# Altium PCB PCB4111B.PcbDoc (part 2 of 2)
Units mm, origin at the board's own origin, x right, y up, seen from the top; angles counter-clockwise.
Board outline 30 x 47 mm, 4 copper layers (Top Layer, Signal Layer 2, Signal Layer 3, Bottom Layer), stack 1.556 mm thick; 81 components, 93 nets, 294 pads, 415 vias.
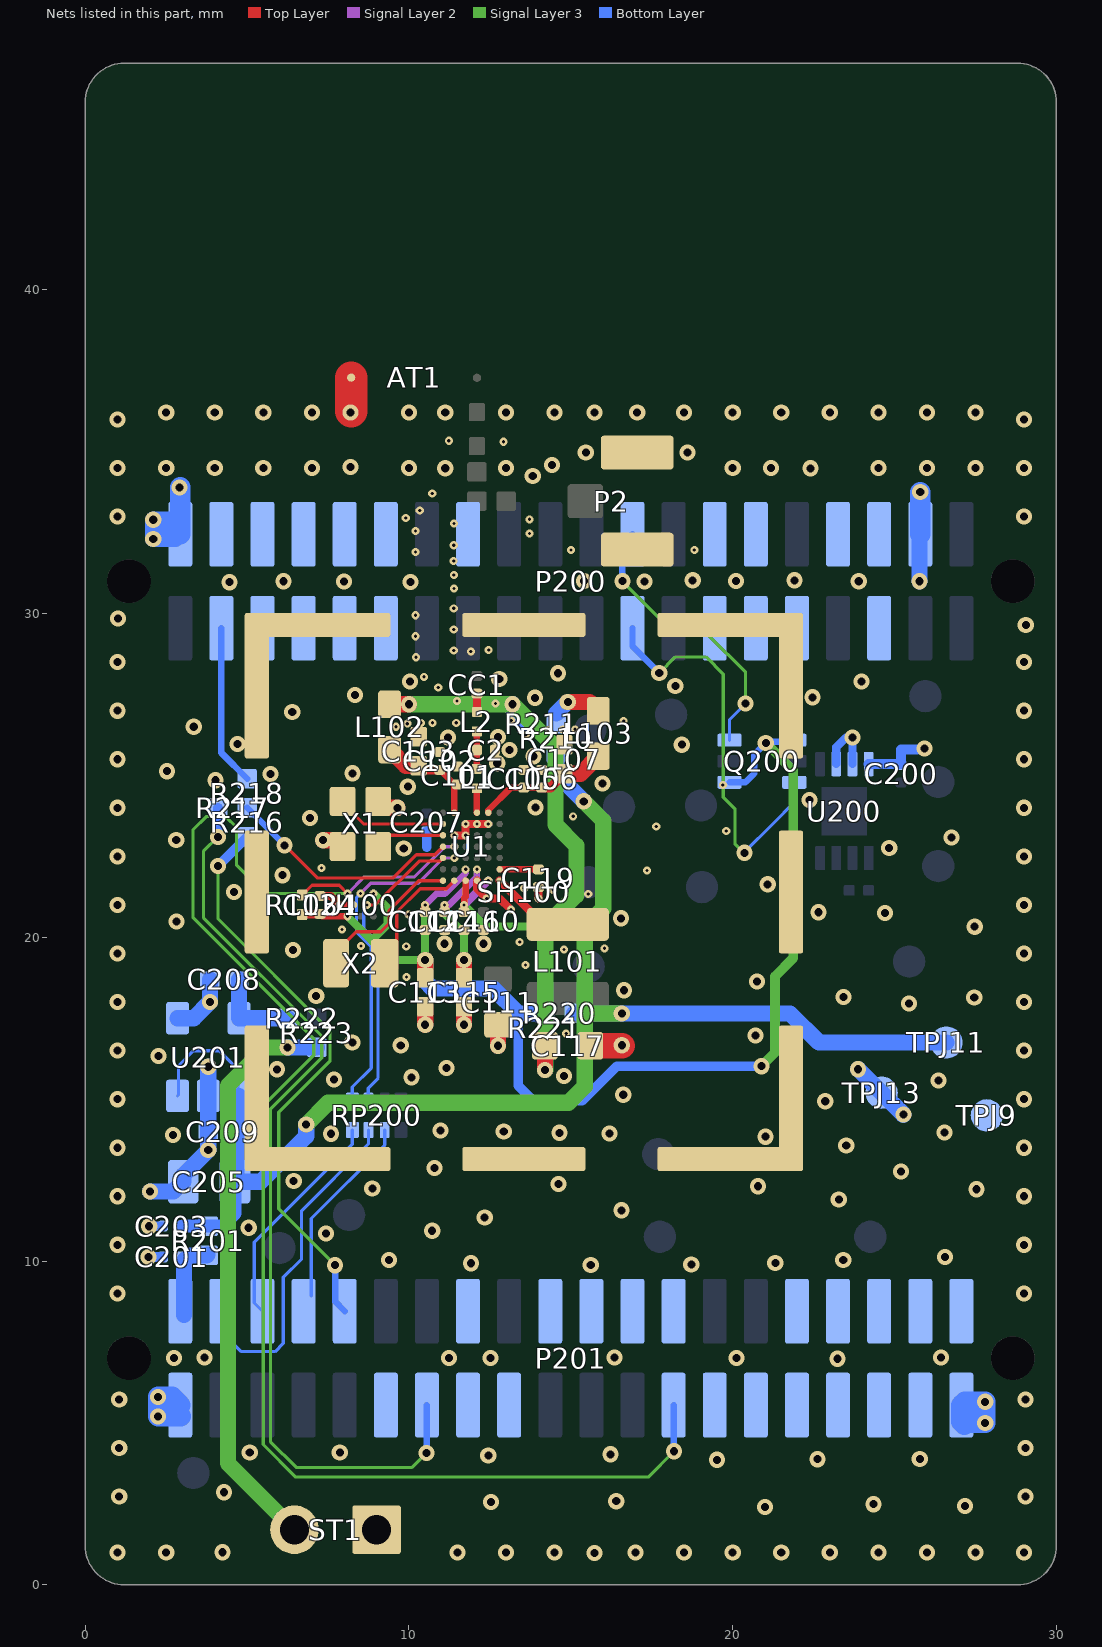
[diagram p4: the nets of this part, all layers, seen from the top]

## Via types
v1: diameter 0.5, hole 0.25, Top Layer to Bottom Layer, tented both sides, 309 vias
v2: diameter 0.25, hole 0.1, Top Layer to Bottom Layer, tented both sides, 63 vias
v3: diameter 0.25, hole 0.1, Top Layer to Signal Layer 2, tented top, 39 vias
v4: diameter 0.25, hole 0.1, Top Layer to Bottom Layer, tented top, 2 vias
v5: diameter 0.25, hole 0.1, Top Layer to Signal Layer 2, tented both sides, 2 vias

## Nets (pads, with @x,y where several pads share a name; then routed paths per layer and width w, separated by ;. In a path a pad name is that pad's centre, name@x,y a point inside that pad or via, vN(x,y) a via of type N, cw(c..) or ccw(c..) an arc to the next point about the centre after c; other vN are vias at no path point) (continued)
EFR32_PC03: RP200.1 U1.C5 U100.C3 | length 10.2
  Signal Layer 2 w0.1: v2(8.5,21.35) 8.817,21.667 10.281,21.667 11.065,22.45 v3(11.4,22.45)
  Bottom Layer w0.1: RP200.1@8.25,14.95 8.247,14.953 8.247,15.376 8.832,15.961 8.832,19.703 8.382,20.153 8.382,21.232 v2(8.5,21.35)
EFR32_PC04: P201.25 R103.1 U1.D5 U100.A3 | length 48.2
  Top Layer w0.1: R103.1@6.7,21.3 7.004,21.604 7.846,21.604 v2(8.1,21.35)
  Signal Layer 2 w0.1: v2(8.1,21.35) 8.617,21.867 10.17,21.867 11.103,22.8 v3(11.4,22.8)
  Signal Layer 3 w0.1: v2(8.1,21.35) 5.546,21.35 4.673,22.223 4.673,23.392 4.336,23.729 3.731,23.729 3.331,23.329 3.331,20.6 7.061,16.871 7.061,16.356 5.496,14.791 5.496,4.332 6.503,3.325 17.388,3.325 v1(18.186,4.123)
  Bottom Layer w0.2: P201.25@18.175,5.55 18.181,5.544 18.181,4.129 v1(18.186,4.123)
EFR32_PC05: RP200.2 U1.C6 U100.D2 | length 9.4
  Top Layer w0.1: v2(8.7,21) 8.959,21 10.313,22.353 10.953,22.353 U1.C6@11.05,22.45
  Bottom Layer w0.1: v2(8.7,21) 8.604,20.904 8.604,20.269 9.047,19.827 9.047,15.651 8.739,15.343 8.739,14.961 RP200.2@8.75,14.95
EFR32_PC06: R216.1 R217.1 R218.1 U1.D6 | length 7.3
  Top Layer w0.1: v1(6.159,22.842) 7.165,21.836 9.512,21.836 10.23,22.553 10.8,22.553 11.047,22.8 U1.D6@11.05,22.8
  Bottom Layer w0.2: R218.1@5.001,24 v1(6.159,22.842)
EFR32_PD00: U1.A6 X2.1 | length 4.4
  Top Layer w0.1: X2.1@7.775,19.577 8.366,20.168 9.124,20.168 9.381,20.425 9.381,20.826 10.305,21.75 U1.A6@11.05,21.75
EFR32_PD01: U1.A5 X2.2 | length 3.9
  Top Layer w0.1: X2.2@9.623,19.046 9.623,20.781 10.342,21.5 11.154,21.5 11.4,21.746 U1.A5@11.4,21.75
GND: AT1.2 C2.2 C101.2 C102.2 C103.2 C105.2 C106.2 C107.2 C110.2 C111.2 C112.2 C113.2 C114.2 C115.2 C116.2 C117.2 C119.2 C124.2 C200.2 C201.2 C203.2 C205.2 C207.2 C208.2 C209.2 P2.2 P2.3 P200.2 P200.38 P201.1 P201.39 SH100.1 ST1.1 TPJ13.1 U1.A3 U1.E4 U1.E5 U1.F2 U1.F3 U1.F4 U100.B2 U200.2 U200.3 U200.4 U201.2 U201.4 X1.2 X1.4 | length 37.7
  Top Layer w0.2: v2(7.86,21) U100.B2@8.3,21
  Top Layer w0.25: C124.2@7.25,21.275 7.585,21.275 v2(7.86,21) ; v2(11.4,23.15) v2(11.75,23.15) v2(11.75,23.5) v2(12.1,23.5) v2(12.45,23.5) ; U1.A3@12.1,21.75 12.1,21.5 v4(12.4,21.2) 12.8,21.2 v4(13.15,20.85) ; v2(14,21.2) C119.2@14,21.55
  Top Layer w0.5: v1(7.35,23) 7.75,23 X1.4@7.95,22.8 ; X1.2@9.05,24.2 9.25,24 v1(9.65,24) ; v1(10.5,17.3) C113.2@10.5,17.85 ; v1(11.7,17.3) C115.2@11.7,17.85 ; v1(12.75,16.65) C111.2@12.75,17.3
  Top Layer w0.8: C117.2@15.6,16.65 v1@16.575,16.65
  Top Layer w1: v1@8.214,36.255 AT1.2@8.214,37.288
  Bottom Layer w0.254: v1(1.95,10.125) v1@2,10.125 ; v1(1.975,11.075) 2.025,11.075 C203.2@2.4,11.075 ; v1@2.025,10.125 v1@2,10.125 ; C201.2@2.4,10.125 v1@2,10.125 ; U200.2@23.2,25.35 23.2,25.875 23.5,26.175 v1(23.7,26.175) U200.3@23.7,25.35
  Bottom Layer w0.3: v1@2.025,10.125 C201.2@2.4,10.125 ; v1@2.025,11.075 C203.2@2.4,11.075 ; 10.55,22.787 C207.2@10.55,23.275
  Bottom Layer w0.305: U200.4@24.2,25.35 25.2,25.35 25.2,25.8 v1@25.7,25.8
  Bottom Layer w0.5: v1(2,12.15) 2.725,12.15 C205.2@3.025,12.45 3.025,12.65 v1(3.8,13.425) C209.2@3.8,14 U201.2@3.8,15.1 v1(3.8,16) ; U201.4@2.85,17.5 3.35,17.5 v1(3.85,18) C208.2@3.85,18.7 ; P200.2@2.935,32.9 v1(2.1,32.9) 2.1,32.6 ; v1(25.775,31) 25.775,32.43 P200.38@25.795,32.45 ; 2.1,32.6 2.785,32.6 P200.2@2.935,32.45 2.785,32.3 v1(2.1,32.3) 2.1,32.6
  Bottom Layer w0.508: v1(23.875,15.925) TPJ13.1@24.6,15.2 v1(25.275,14.525)
  Bottom Layer w0.635: P201.1@2.9,5.25 2.95,5.2 v1(2.25,5.2) v1(2.25,5.8) 2.685,5.8 P201.1@2.935,5.55 ; P200.2@2.935,32.45 2.935,32.9 v1@2.935,33.895 ; P200.38@25.795,32.45 v1(25.795,33.755) ; P201.39@27.065,5.55 27.165,5.65 v1(27.8,5.65) ; P201.39@27.065,5.55 27.7,5.55 v1(27.8,5.65) ; P201.39@27.065,5.55 27.065,5.035 27.15,4.95 27.2,5 v1(27.8,5) v1(27.8,5.65)
  other v1: 15.73,0.979 1,1 2.5,1 4.239,1.003 11.5,1 13,1 14.5,1 17,1 18.5,1 20,1 21.5,1 23,1 24.5,1 26,1 27.5,1 29,1 20.996,2.4 27.178,2.433 24.354,2.488 12.531,2.558 16.403,2.581 1.048,2.726 29.048,2.722 4.287,2.857 19.516,3.859 22.62,3.878 25.78,3.887 12.451,3.992 16.226,4.029 5.081,4.081 7.863,4.083 1.048,4.226 29.048,4.222 1.048,5.726 29.048,5.722 23.234,6.98 2.743,7.005 11.232,7.009 12.514,7.004 20.12,7 3.682,7.02 16.347,7.024 26.433,7.023 1,9 29,9 15.615,9.878 18.721,9.893 11.915,9.931 21.316,9.939 23.415,10.032 9.381,10.033 26.557,10.127 1,10.5 29,10.5 7.44,10.853 10.716,10.935 5.049,11.028 12.338,11.343 16.57,11.566 23.278,11.901 1,12 29,12 27.527,12.216 8.867,12.237 20.777,12.311 14.622,12.377 6.438,12.476 25.202,12.761 10.792,12.871 1,13.5 29,13.5 23.509,13.572 21.01,13.84 2.711,13.896 7.588,13.932 16.194,13.942 14.648,13.96 26.547,13.971 12.929,13.997 10.975,14.027 22.859,14.936 1,15 29,15 16.618,15.137 26.358,15.575 7.684,15.609 10.075,15.675 14.792,15.718 5.926,15.922 11.159,15.966 2.26,16.337 1,16.5 29,16.5 9.745,16.664 16.575,16.665 8.249,16.751 20.707,16.97 25.449,17.954 1,18 29,18 23.424,18.153 27.463,18.142 7.133,18.19 16.639,18.364 20.748,18.632 1,19.5 29,19.5 6.415,19.605 11.1,19.8 12.3,19.8 27.475,20.329 2.822,20.485 16.546,20.587 24.703,20.749 22.652,20.775 1,21 29,21 4.599,21.4 21.081,21.637 6.089,21.919 1,22.5 29,22.5 9.838,22.738 24.835,22.757 2.812,23.001 26.755,23.087 6.942,23.682 1,24 29,24 13.913,24.011 22.376,24.243 9.964,24.652 15.978,24.75 4.027,24.851 5.72,25.047 8.254,25.065 2.521,25.132 12.727,25.378 1,25.5 29,25.5 13.844,25.592 13.108,25.784 25.927,25.836 18.429,25.95 4.707,25.975 11.21,26.176 12.752,26.191 3.351,26.504 6.393,26.957 1,27 29,27 13.889,27.398 22.462,27.414 8.335,27.485 18.227,27.76 10.03,27.906 23.979,27.907 12.787,27.976 14.608,28.156 1,28.5 29,28.5 29.055,29.645 1.011,29.852 4.459,30.97 10.046,30.974 6.127,31 7.991,30.989 15.405,31.009 17.279,30.994 20.106,31.007 23.895,31 18.764,31.028 21.911,31.028 1,33 29,33 2.911,33.895 13.824,34.252 11.12,34.491 22.403,34.488 1,34.5 2.5,34.5 4,34.5 5.5,34.5 7,34.5 10,34.5 13,34.5 20,34.5 21.187,34.501 24.5,34.5 26,34.5 27.5,34.5 29,34.5 8.197,34.528 14.421,34.591 15.463,34.975 18.606,34.975 1,36 29,36 2.5,36.211 4,36.211 5.5,36.211 7,36.211 8.197,36.211 10,36.211 11.12,36.211 13,36.211 14.5,36.211 15.73,36.211 17.05,36.211 18.5,36.211 20,36.211 21.5,36.211 23,36.211 24.5,36.211 26,36.211 27.5,36.211
  other v2: 14.855,17.031 9.921,18.776 13.602,19.143 14.789,19.626 16.038,19.659 9.916,19.722 13.419,19.853 7.93,20.242 9.986,20.711 14.445,21.461 13.561,21.516 7.295,22.144 19.8,23.286 15.072,23.736 9.598,26.505 9.95,26.6 10.375,26.625 10.725,26.625 11.46,26.624 16.633,26.679 10.905,27.719 12.461,28.874 11.393,30.773 11.386,31.191 15.005,31.962 18.815,31.961 13.725,32.475 13.722,32.91 9.9,32.95
  other v3: 8.516,19.729 15.539,21.334 17.351,22.062 17.639,23.427 19.695,24.708 13.606,26.25 14.325,26.425 14.75,26.425 15.125,26.425 13.162,26.697 12.677,27.225 11.485,27.302 10.462,28.046 10.22,28.65 11.911,28.826 11.384,28.862 10.199,29.299 11.384,29.512 10.199,29.949 11.384,30.162 11.381,31.623 10.199,31.899 11.384,32.112 10.199,32.549 11.389,32.78 10.333,33.185 10.72,33.708 12.924,35.308 11.232,35.338
N16773989: U1.F6 X1.3 | length 3.4
  Top Layer w0.1: X1.3@7.95,24.2 7.95,24.149 8.599,23.5 U1.F6@11.05,23.5
N16774051: U1.E6 X1.1 | length 2
  Top Layer w0.1: X1.1@9.107,23.011 9.245,23.15 U1.E6@11.05,23.15
N16774211: C101.1 C102.1 C103.1 L102.2 U1.G5 | length 3.3
  Top Layer w0.2: C102.1@10.95,25.175 11.4,24.725 U1.G5@11.4,23.85
  Top Layer w0.3: C103.1@10.3,25.3 10.425,25.175 C102.1@10.95,25.175
  Top Layer w0.5: L102.2@9.4,25.8 9.9,25.3 C103.1@10.3,25.3
N16774267: C105.1 C106.1 C107.1 L103.2 U1.G2 | length 4.2
  Top Layer w0.2: U1.G2@12.45,23.85 12.45,23.924 13.151,24.625 C105.1@13.55,24.625 C106.1@14.1,24.625
  Top Layer w0.3: C106.1@14.1,24.625 14.375,24.625 C107.1@14.8,25.05
  Top Layer w0.5: C107.1@14.8,25.05 15.3,25.05 L103.2@15.85,25.6
N16774345: L1.1 U1.G3 | length 0.8
  Top Layer w0.2: U1.G3@12.1,23.85 L1.1@12.1,24.6
N16774387: C2.1 L1.2 L2.1 | length 1.2
  Top Layer w0.2: L1.2@12.1,25.2 L2.1@12.1,26.36
N16775238: C119.1 U1.B1 | length 1.2
  Top Layer w0.2: U1.B1@12.8,22.1 C119.1@14,22.1
N16775410: L101.1 U1.A1 | length 2
  Top Layer w0.25: U1.A1@12.8,21.75 L101.1@14.19,20.36
N16787268: CC1.1 L2.2 | length 0.6
  Top Layer w0.25: L2.2@12.1,26.96 CC1.1@12.1,27.525
N16950627: C208.1 R222.1 U201.5 | length 2.7
  Bottom Layer w0.5: C208.1@4.75,18.7 U201.5@4.75,17.5 R222.1@6.25,17.5
N16950686: R223.1 ST1.2 | length 17.8
  Signal Layer 3 w0.5: v1(6.25,16.6) 5.59,16.6 4.407,15.417 4.407,3.753 ST1.2@6.46,1.7
  Bottom Layer w0.5: v1(6.25,16.6) R223.1@7.15,16.6
PAVDD: L103.1 R210.1 R211.2 | length 1.6
  Top Layer w0.5: v1(14.907,27.272) 15.579,27.272 L103.1@15.85,27
  Bottom Layer w0.5: 14.55,26.914 v1(14.907,27.272)
USB_VBUS: P200.35
USB_VREG: P200.36
VAVDD: C112.1 C113.1 C114.1 C115.1 C124.1 Q200.1 Q200.4 R103.2 R220.1 R221.2 U1.B3 U1.B4 U100.A1 U100.E3 | length 44.4
  Top Layer w0.2: C124.1@7.25,20.725 7.325,20.65 v2(8.1,20.65)
  Top Layer w0.25: R103.2@6.712,20.713 C124.1@7.238,20.713 ; C112.1@10.5,20.775 v2(10.5,21) ; C114.1@11.1,20.775 v2@11.1,20.989
  Top Layer w0.5: C113.1@10.5,18.75 v1(10.5,19.3) ; C115.1@11.7,18.755 v1(11.7,19.3)
  Signal Layer 2 w0.2: v2(10.5,21) 10.848,21.348 11.111,21.348 11.75,21.988 v3(11.75,22.1) ; v2(11.1,21) 11.238,21 12.1,21.862 v3(12.1,22.1)
  Signal Layer 3 w0.25: v2(8.1,20.65) 8.84,19.91 ; v2(8.9,21.35) 9.338,20.912 9.338,20.4 8.844,19.906 9.45,19.3 v1(10.5,19.3) v2(10.5,21) ; v2(11.1,21) 11.1,20.726 11.7,20.126 v1(11.7,19.3)
  Signal Layer 3 w0.3: v1(20.886,16.019) 21.309,16.442 21.309,18.795 21.867,19.353 21.867,25.158 v1(21.023,26.001)
  Bottom Layer w0.2: Q200.1@19.903,24.789 20.394,24.789 20.667,25.062 20.667,25.645 v1(21.023,26.001) 21.067,26.045 21.859,26.045 Q200.4@21.903,26.089
  Bottom Layer w0.3: 13.375,17.65 13.375,15.425 13.853,14.948 15.351,14.948 16.423,16.019 v1(20.886,16.019)
  Bottom Layer w0.5: v1(10.5,19.3) 10.5,18.645 10.727,18.418 11.672,18.418 ; v1(11.7,19.3) 11.7,18.446 11.672,18.418 ; R221.2@14.2,17.65 13.375,17.65 12.607,18.418 11.672,18.418
VDCDC: C116.1 C117.1 L102.1 R211.1 R221.1 U1.A2 U1.A4 | length 23.5
  Top Layer w0.2: v2(11.7,21) 11.7,21.206 11.75,21.256 U1.A4@11.75,21.75
  Top Layer w0.25: C116.1@11.7,20.775 v2(11.7,21)
  Top Layer w0.5: L102.1@9.4,27.2 v1(10,27.2) ; v1(14.2,15.9) C117.1@14.2,16.65
  Signal Layer 2 w0.25: v2(11.7,21) v3(12.45,21.75)
  Signal Layer 3 w0.25: v2(11.7,21) 12.367,20.334 14.207,20.334
  Signal Layer 3 w0.5: v1(10,27.2) v1(13.2,27.2) 14.526,25.874 14.526,23.477 15.171,22.832 15.171,21.298 14.207,20.334 v1@14.207,15.9
  Bottom Layer w0.5: v1(13.2,27.2) 13.2,27.05 R211.1@13.65,26.6 ; v1(14.2,15.9) R221.1@14.2,16.75
VMCU: C203.1 C205.1 C209.1 R201.2 R210.2 R220.2 TPJ11.1 U201.1 U201.3 | length 46
  Signal Layer 3 w0.5: v1(6.824,14.215) 7.499,14.891 14.928,14.891 15.432,15.394 15.432,17.65 ; v1(15.4,24.2) 16.002,23.598 16.002,20.892 15.432,20.322 15.432,17.65 ; v1(16.575,17.65) 15.432,17.65
  Bottom Layer w0.1: U201.3@2.85,15.1 2.88,15.13 2.88,16.034 3.341,16.495 4.138,16.495 4.716,15.918 4.716,15.084 U201.1@4.725,15.075
  Bottom Layer w0.4: C203.1@3,11.075 R201.2@3.8,11.075 4.237,11.075 4.625,11.463 C205.1@4.625,12.45
  Bottom Layer w0.5: U201.1@4.75,15.1 4.725,15.075 4.725,14 C209.1@4.7,14 4.663,14 4.663,12.487 C205.1@4.625,12.45 5.418,12.45 6.824,13.856 v1(6.824,14.215) ; R210.2@14.55,25.7 14.55,25.05 v1(15.4,24.2) ; R220.2@15.1,17.65 v1(16.575,17.65) 21.766,17.65 22.666,16.75 TPJ11.1@26.6,16.75
VMCU_IN: C201.1 P201.2 R201.1 | length 2.5
  Bottom Layer w0.4: R201.1@3.775,10.15 R201.1@3.8,10.175
  Bottom Layer w0.5: P201.2@3.05,8.335 3.05,10 3.225,10.175 3.75,10.175 R201.1@3.775,10.2
VRF: TPJ9.1
VRF_IN: P201.40
WSTK_F3: P200.16
WSTK_F10: P200.23 Q200.6 | length 12.8
  Signal Layer 3 w0.1: v1(17.733,28.161) 18.232,28.661 19.179,28.661 19.708,28.131 19.708,24.327 20.075,23.96 20.075,22.869 20.335,22.61 v1(20.367,22.61)
  Bottom Layer w0.1: v1(20.367,22.61) 20.367,22.636 21.246,23.516 21.903,24.172 Q200.6@21.903,24.789
  Bottom Layer w0.2: P200.23@16.905,29.55 16.905,28.989 v1(17.733,28.161)
WSTK_F11: P200.24 Q200.3 | length 8.9
  Signal Layer 3 w0.1: v1(16.593,31.001) 18.26,29.334 19.249,29.334 20.398,28.185 v1(20.398,27.223)
  Bottom Layer w0.1: Q200.3@19.903,26.089 19.903,26.727 v1(20.398,27.223)
  Bottom Layer w0.2: v1(16.593,31.001) 16.593,32.138 P200.24@16.905,32.45
WSTK_F14: P200.27
WSTK_F15: P200.28
WSTK_F16: P200.29
WSTK_F17: P200.30
WSTK_F18: P200.31
WSTK_F21: P200.34
WSTK_P1: P201.4 RP200.7 | length 10.6
  Bottom Layer w0.1: P201.4@4.205,8.45 4.205,7.82 4.824,7.201 5.863,7.201 6.115,7.453 6.115,9.495 6.681,10.061 6.681,11.554 8.75,13.623 RP200.7@8.75,14.05
WSTK_P3: P201.6 RP200.8 | length 7
  Bottom Layer w0.1: P201.6@5.475,8.45 5.222,8.703 5.222,10.577 8.25,13.605 RP200.8@8.25,14.05
WSTK_P5: P201.8 RP200.6 | length 6.1
  Bottom Layer w0.1: P201.8@6.982,8.921 6.982,11.314 9.25,13.581 RP200.6@9.25,14.05
WSTK_P7: P201.10 R216.2 | length 18
  Signal Layer 3 w0.1: v1(4.1,22.2) 4.1,20.575 7.557,17.119 7.557,16.173 5.977,14.593 5.977,11.614 v1(7.719,9.872)
  Bottom Layer w0.2: v1(7.719,9.872) 7.719,8.746 P201.10@8.015,8.45
  Bottom Layer w0.3: v1(4.1,22.2) R216.2@5.001,23.1
WSTK_P8: P201.11
WSTK_P10: P201.13 R217.2 | length 28.8
  Signal Layer 3 w0.1: v1(4.1,23.103) 3.65,22.653 3.65,20.61 7.309,16.952 7.309,16.281 5.721,14.693 5.721,4.422 6.52,3.623 10.096,3.623 v1(10.538,4.065)
  Bottom Layer w0.2: v1(10.538,4.065) 10.547,4.073 10.547,5.541 P201.13@10.555,5.55
  Bottom Layer w0.3: v1(4.1,23.103) R217.2@4.1,24
WSTK_P12: P201.15
WSTK_P13: P201.16
WSTK_P14: P201.17
WSTK_P17: P201.20
WSTK_P19: P201.22
WSTK_P21: P201.24
WSTK_P23: P201.26
WSTK_P24: P201.27
WSTK_P26: P201.29
WSTK_P28: P201.31
WSTK_P29: P201.32
WSTK_P30: P201.33
WSTK_P31: P201.34
WSTK_P32: P201.35
WSTK_P33: P201.36
WSTK_P34: P201.37
WSTK_P35: P201.38
WSTK_P36: P200.3 R218.2 | length 5
  Bottom Layer w0.2: P200.3@4.205,29.55 4.205,25.695 R218.2@5.001,24.9
WSTK_P37: P200.4
WSTK_P38: P200.5
WSTK_P39: P200.6
WSTK_P40: P200.7
WSTK_P41: P200.8
WSTK_P42: P200.9
WSTK_P43: P200.10
WSTK_P44: P200.11
WSTK_P45: P200.12
pads on no net: P200.M1 P200.M2 P201.M1 P201.M2 RP200.4 RP200.5 TPJ4.1 TPJ18.1 TPJ19.1 TPJ20.1 U100.C1 U200.9

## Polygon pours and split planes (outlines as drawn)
GND on Signal Layer 2 "GND_L2" (solid, remove dead copper, pour order 48): 0,0 0,36.6 30,36.6 30,0
GND on Top Layer "GND_L1" (solid, remove dead copper, pour order 56): 0,0 0,36.6 30,36.6 30,0
GND on Signal Layer 3 "GND_L3" (solid, remove dead copper, pour order 52): 0,0 0,36.6 30,36.6 30,0
GND on Bottom Layer "GND_L4" (solid, remove dead copper, pour order 54): 0,0 0,36.6 30,36.6 30,0

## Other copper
Top Layer:
  rectangle net GND: 14.354,26.069 15.221,26.439
  rectangle net GND: 9.854,26.319 10.721,26.689
  pour cut-out: 10.12,21.656 12.2,21.656 12.2,21.296 12.535,21.296 13.255,20.576 13.255,19.64 13.307,19.588 13.307,17.194 12.324,17.194 12.098,17.42 10.196,17.42 10.12,17.496
  pour cut-out: 14.3,25.7 14.592,25.7 14.592,25.328 14.3,25.328
  region net GND: 10.909,25.57 10.78,25.699 10.78,26.443 11.669,26.443 11.669,25.225 11.33,25.225 11.33,25.421 11.181,25.57
  region net GND: 12.507,26.224 12.507,25.28 12.95,25.28 13.28,25.61 13.28,25.945 13.001,26.224
  pour cut-out: 12.537,26.922 13.484,25.976 13.484,24.401 11.666,24.401 11.666,28.405 11.751,28.491 12.349,28.491 12.537,28.303
  region net GND: 13.509,25.02 13.38,25.149 13.38,25.357 13.484,25.461 13.484,25.893 14.42,25.893 14.42,25.485 14.269,25.334 14.269,25.104 14.185,25.02
  region net GND: 10.331,20.25 10.461,20.38 12.373,20.38 12.47,20.282 12.47,20.073 12.603,19.941 12.603,19.683 12.417,19.497 12.148,19.497 11.916,19.728 11.518,19.728 11.286,19.497 10.835,19.497 10.331,20.001
  pour cut-out: 9.39,22.185 7.469,22.185 6.922,22.732 6.922,23.186 7.248,23.512 7.248,24.487 7.551,24.79 9.459,24.79 10.041,24.208 10.041,23.404 9.587,23.404 9.587,22.382
  pour cut-out: 11.54,36.835 12.66,36.835 12.66,34.365 12.99,34.035 13.24,34.035 13.24,32.915 11.54,32.915
Signal Layer 2:
  pour cut-out: 18.252,32.625 18.252,34.325 16.149,34.325 14.595,34.322 14.595,32.625 16.148,32.625
  pour cut-out: 11.54,36.307 12.66,36.307 12.66,34.365 12.99,34.035 13.45,34.035 13.45,32.915 11.54,32.915
Bottom Layer:
  pour cut-out: 9.284,4.452 9.285,4.633 8.088,4.633 8.088,4.454
  pour cut-out: 9.323,9.371 9.323,9.553 8.126,9.553 8.126,9.374
  pour cut-out: 5.424,4.443 5.425,4.624 4.228,4.624 4.228,4.445
  pour cut-out: 5.433,9.372 5.433,9.553 4.236,9.553 4.236,9.374
  pour cut-out: 9.548,32.755 9.548,32.573 10.332,32.573 10.332,32.753
  pour cut-out: 9.299,30.648 9.298,30.469 10.292,30.469 10.292,30.646
  pour cut-out: 13.342,32.158 13.341,31.977 14.126,31.977 14.126,32.156
  pour cut-out: 15.89,33.551 15.889,33.369 16.821,33.369 16.821,33.549
  pour cut-out: 17.176,30.657 17.176,30.456 21.986,30.456 21.986,30.648
  pour cut-out: 7.938,14.18 10.062,14.18 10.062,14.78 7.938,14.78

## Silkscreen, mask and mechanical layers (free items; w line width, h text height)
Top Overlay:
  lines w0.2: 3.282,1.647 4.907,1.647 ; 4.094,0.834 4.094,2.459 ; 10.557,1.709 12.182,1.709
  text ".CreativeName" at 1,43 h3.2
  text ".2G4freq" at 1,41 h1.9
  text ".2G4power" at 1,39.5 h1.9
  text ".Package" at 1,38 h1.9
Bottom Overlay:
  lines w0.15: 1.5,40 1.5,39 2.5,39 ; 1.5,44 1.5,45 2.5,45 ; 19.5,39 20.5,39 20.5,40 ; 19.5,45 20.5,45 20.5,44
  lines w0.152: 3.577,23.805 3.577,23.505 3.877,23.505 ; 3.577,24.205 3.577,24.505 3.877,24.505 ; 4.177,23.505 4.477,23.505 4.477,23.205 ; 4.177,24.505 4.477,24.505 4.477,24.805 ; 4.477,22.905 4.477,22.605 4.777,22.605 ; 4.477,25.105 4.477,25.405 4.777,25.405 ; 5.202,22.605 5.502,22.605 5.502,22.905 ; 5.202,25.405 5.502,25.405 5.502,25.105 ; 5.402,23.555 5.502,23.555 5.502,23.805 ; 5.402,24.455 5.502,24.455 5.502,24.205 ; 5.745,17.295 5.745,16.995 6.045,16.995 ; 5.745,17.695 5.745,17.995 6.045,17.995 ; 6.345,16.995 6.645,16.995 6.645,16.695 ; 6.645,16.395 6.645,16.095 6.945,16.095 ; 6.695,17.895 6.695,17.995 6.945,17.995 ; 7.345,16.095 7.645,16.095 7.645,16.395 ; 7.345,17.995 7.665,17.995 7.665,17.699 ; 7.655,16.882 7.655,17.178 ; 13.151,26.395 13.151,26.095 13.451,26.095 ; 13.151,26.795 13.151,27.095 13.451,27.095 ; 13.709,16.537 13.709,16.237 14.009,16.237 ; 13.709,17.437 13.709,17.187 13.809,17.187 ; 13.709,17.837 13.709,18.112 13.934,18.112 ; 13.751,26.095 14.051,26.095 14.051,25.795 ; 14.051,25.495 14.051,25.195 14.351,25.195 ; 14.101,26.995 14.101,27.095 14.351,27.095 ; 14.409,16.237 14.709,16.237 14.709,16.537 ; 14.409,18.112 14.709,18.112 ; 14.709,16.837 14.709,17.137 15.009,17.137 ; 14.751,25.195 15.051,25.195 15.051,25.495 ; 14.751,27.095 14.867,27.095 ; 15.309,17.137 15.609,17.137 15.609,17.437 ; 15.309,18.137 15.609,18.137 15.609,17.837
  text "BOARD INFO" at 20.55,45.35 h1.6
  text "VDCDC" at 12.935,26.155 h1.2
  text "JOYSTICK" at 5.97,25.721 h1.2
  text "EXP5" at 3.371,23.649 h1.2
  text "PAVDD / Conf." at 13.881,23.524 h1.6
  text "VMCU" at 13.946,21.914 h1.2 r270
  text "PC06" at 5.852,21.767 h1.6 r270
  text "EXP10" at 5.153,21.53 h1.2
  text "1.5V Input" at 9.632,19.001 h1.6
  text "LDO" at 7.607,18.201 h1.2
  text "VMCU" at 18.991,17.224 h1.2
  text "'.BoardName' Rev. '.BoardRevision'" at 28,15.7 h1.52 r270
  text "IOVDD / Conf." at 19.013,13.878 h1.6
  text "BAT" at 6.702,13.842 h1.2 r270
  text "VDCDC" at 13.742,12.198 h1.2 r270
Top Solder:
  the board outline again, w0.8
Bottom Solder:
  the board outline again, w0.8
BOARD OUTLINE 1:
  the board outline again, w0.1
Mechanical 2:
  lines w0.1: -0.5,0 0.5,0 ; 0,-0.5 0,0.5
Mechanical 11:
  the board outline again, w0.1
Mechanical 12:
  the board outline again, w0.1
Mechanical 26:
  lines w0.2: -117.419,-38.232 -115.794,-38.232 ; -117.419,8.443 -115.794,8.443 ; -117.419,55.118 -115.794,55.118 ; -62.769,-86.482 -62.769,-84.882 ; -62.769,101.818 -62.769,103.418 ; -9.744,-86.482 -9.744,-84.882 ; -9.744,101.818 -9.744,103.418 ; 43.281,-86.482 43.281,-84.882 ; 43.281,101.818 43.281,103.418 ; 96.306,-86.482 96.306,-84.882 ; 96.306,101.818 96.306,103.418 ; 149.331,-38.207 150.956,-38.207 ; 149.331,8.468 150.956,8.468 ; 149.331,55.143 150.956,55.143 ; 150.956,-86.482 -117.419,-86.482 -117.419,103.418 150.956,103.418 150.956,-86.457 ; -115.794,-84.882 -115.794,101.818 149.331,101.818 149.331,-84.882 -115.794,-84.882
  text "5" at -89.444,102.343 h0.5
  text "4" at -36.419,102.318 h0.5
  text "3" at 16.606,102.318 h0.5
  text "2" at 69.631,102.318 h0.5
  text "1" at 122.756,102.318 h0.5
  text "D" at 150.006,78.218 h0.5
  text "D" at -116.744,78.193 h0.5
  text "C" at 150.006,31.518 h0.5
  text "C" at -116.744,31.493 h0.5
  text "B" at 150.006,-15.157 h0.5
  text "B" at -116.744,-15.182 h0.5
  text "A" at 150.006,-61.807 h0.5
  text "A" at -116.744,-61.832 h0.5
  text "5" at -89.444,-85.957 h0.5
  text "4" at -36.419,-85.982 h0.5
  text "3" at 16.606,-85.982 h0.5
  text "2" at 69.631,-85.982 h0.5
  text "1" at 122.756,-85.982 h0.5
Mechanical 27:
  drawing of 28 lines, arcs and shapes, not listed
  text "Board Title" at 79.731,-59.932 h2.5
  text ".BoardTitle" at 81.131,-65.482 h3.3
  text "Page Title" at 79.731,-69.657 h2.5
  text "Designed:" at 47.481,-73.407 h1.7
  text "Approved:" at 63.681,-73.407 h1.7
  text "Top Assembly" at 81.131,-73.557 h3.2
  text ".DrawnByIn" at 49.006,-75.907 h2.2
  text "RGU" at 65.056,-75.907 h2.2
  text "Revision" at 137.631,-76.682 h1.7
  text "Document number" at 79.731,-76.957 h2.35
  text "Size" at 47.481,-78.157 h1.7
  text "BOM Doc. No:" at 52.406,-78.157 h1.7
  text ".BoardRevision" at 137.906,-79.732 h2.7
  text ".BoardName" at 81.131,-79.832 h3.2
  text "A4" at 48.056,-80.007 h2
  text "<>" at 52.981,-80.007 h2
  text "Sheet Modified Date:" at 107.581,-82.357 h1.7
  text "Sheet" at 137.631,-82.357 h1.7
  text "'.Print_Date'" at 108.706,-84.307 h1.7
  text "1" at 138.831,-84.307 h1.7
  text "of" at 141.956,-84.307 h1.7
  text "2" at 144.681,-84.307 h1.7
Mechanical 28:
  lines w0.2: -117.419,-38.232 -115.794,-38.232 ; -117.419,8.443 -115.794,8.443 ; -117.419,55.118 -115.794,55.118 ; -62.769,-86.482 -62.769,-84.882 ; -62.769,101.818 -62.769,103.418 ; -9.744,-86.482 -9.744,-84.882 ; -9.744,101.818 -9.744,103.418 ; 43.281,-86.482 43.281,-84.882 ; 43.281,101.818 43.281,103.418 ; 96.306,-86.482 96.306,-84.882 ; 96.306,101.818 96.306,103.418 ; 149.331,-38.207 150.956,-38.207 ; 149.331,8.468 150.956,8.468 ; 149.331,55.143 150.956,55.143 ; 150.956,-86.482 -117.419,-86.482 -117.419,103.418 150.956,103.418 150.956,-86.457 ; -115.794,-84.882 -115.794,101.818 149.331,101.818 149.331,-84.882 -115.794,-84.882
  text "5" at -89.119,102.343 h0.5
  text "4" at -36.094,102.318 h0.5
  text "3" at 16.931,102.318 h0.5
  text "2" at 69.956,102.318 h0.5
  text "1" at 122.931,102.318 h0.5
  text "D" at 150.331,78.218 h0.5
  text "D" at -116.419,78.193 h0.5
  text "C" at 150.331,31.518 h0.5
  text "C" at -116.419,31.493 h0.5
  text "B" at 150.331,-15.157 h0.5
  text "B" at -116.419,-15.182 h0.5
  text "A" at 150.331,-61.807 h0.5
  text "A" at -116.419,-61.832 h0.5
  text "5" at -89.119,-85.957 h0.5
  text "4" at -36.094,-85.982 h0.5
  text "3" at 16.931,-85.982 h0.5
  text "2" at 69.956,-85.982 h0.5
  text "1" at 122.931,-85.982 h0.5
Mechanical 29:
  drawing of 28 lines, arcs and shapes, not listed
  text "Board Title" at -46.194,-59.932 h2.5
  text ".BoardTitle" at -47.594,-65.482 h3.3
  text "Page Title" at -46.194,-69.657 h2.5
  text "Approved:" at -30.144,-73.407 h1.7
  text "Designed:" at -13.944,-73.407 h1.7
  text "Bottom Assembly" at -47.594,-73.557 h3.2
  text "RGU" at -31.519,-75.907 h2.2
  text ".DrawnByIn" at -15.469,-75.907 h2.2
  text "Revision" at -104.094,-76.682 h1.7
  text "Document number" at -46.194,-76.957 h2.35
  text "BOM Doc. No:" at -18.869,-78.157 h1.7
  text "Size" at -13.944,-78.157 h1.7
  text ".BoardRevision" at -104.359,-79.732 h2.7
  text ".BoardName" at -47.594,-79.832 h3.2
  text "<>" at -19.444,-80.007 h2
  text "A4" at -14.519,-80.007 h2
  text "Sheet" at -104.094,-82.357 h1.7
  text "Sheet Modified Date:" at -74.044,-82.357 h1.7
  text "2" at -111.144,-84.307 h1.7
  text "of" at -108.419,-84.307 h1.7
  text "2" at -105.294,-84.307 h1.7
  text "'.Print_Date'" at -75.169,-84.307 h1.7
Mechanical 30:
  lines w0.2: -121.769,-92.957 161.731,-92.957 161.731,107.518 -121.769,107.518 -121.769,-92.957
Mechanical 31:
  text "Blind vias between TOP and L1" at -8.823,145.721 h2.3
